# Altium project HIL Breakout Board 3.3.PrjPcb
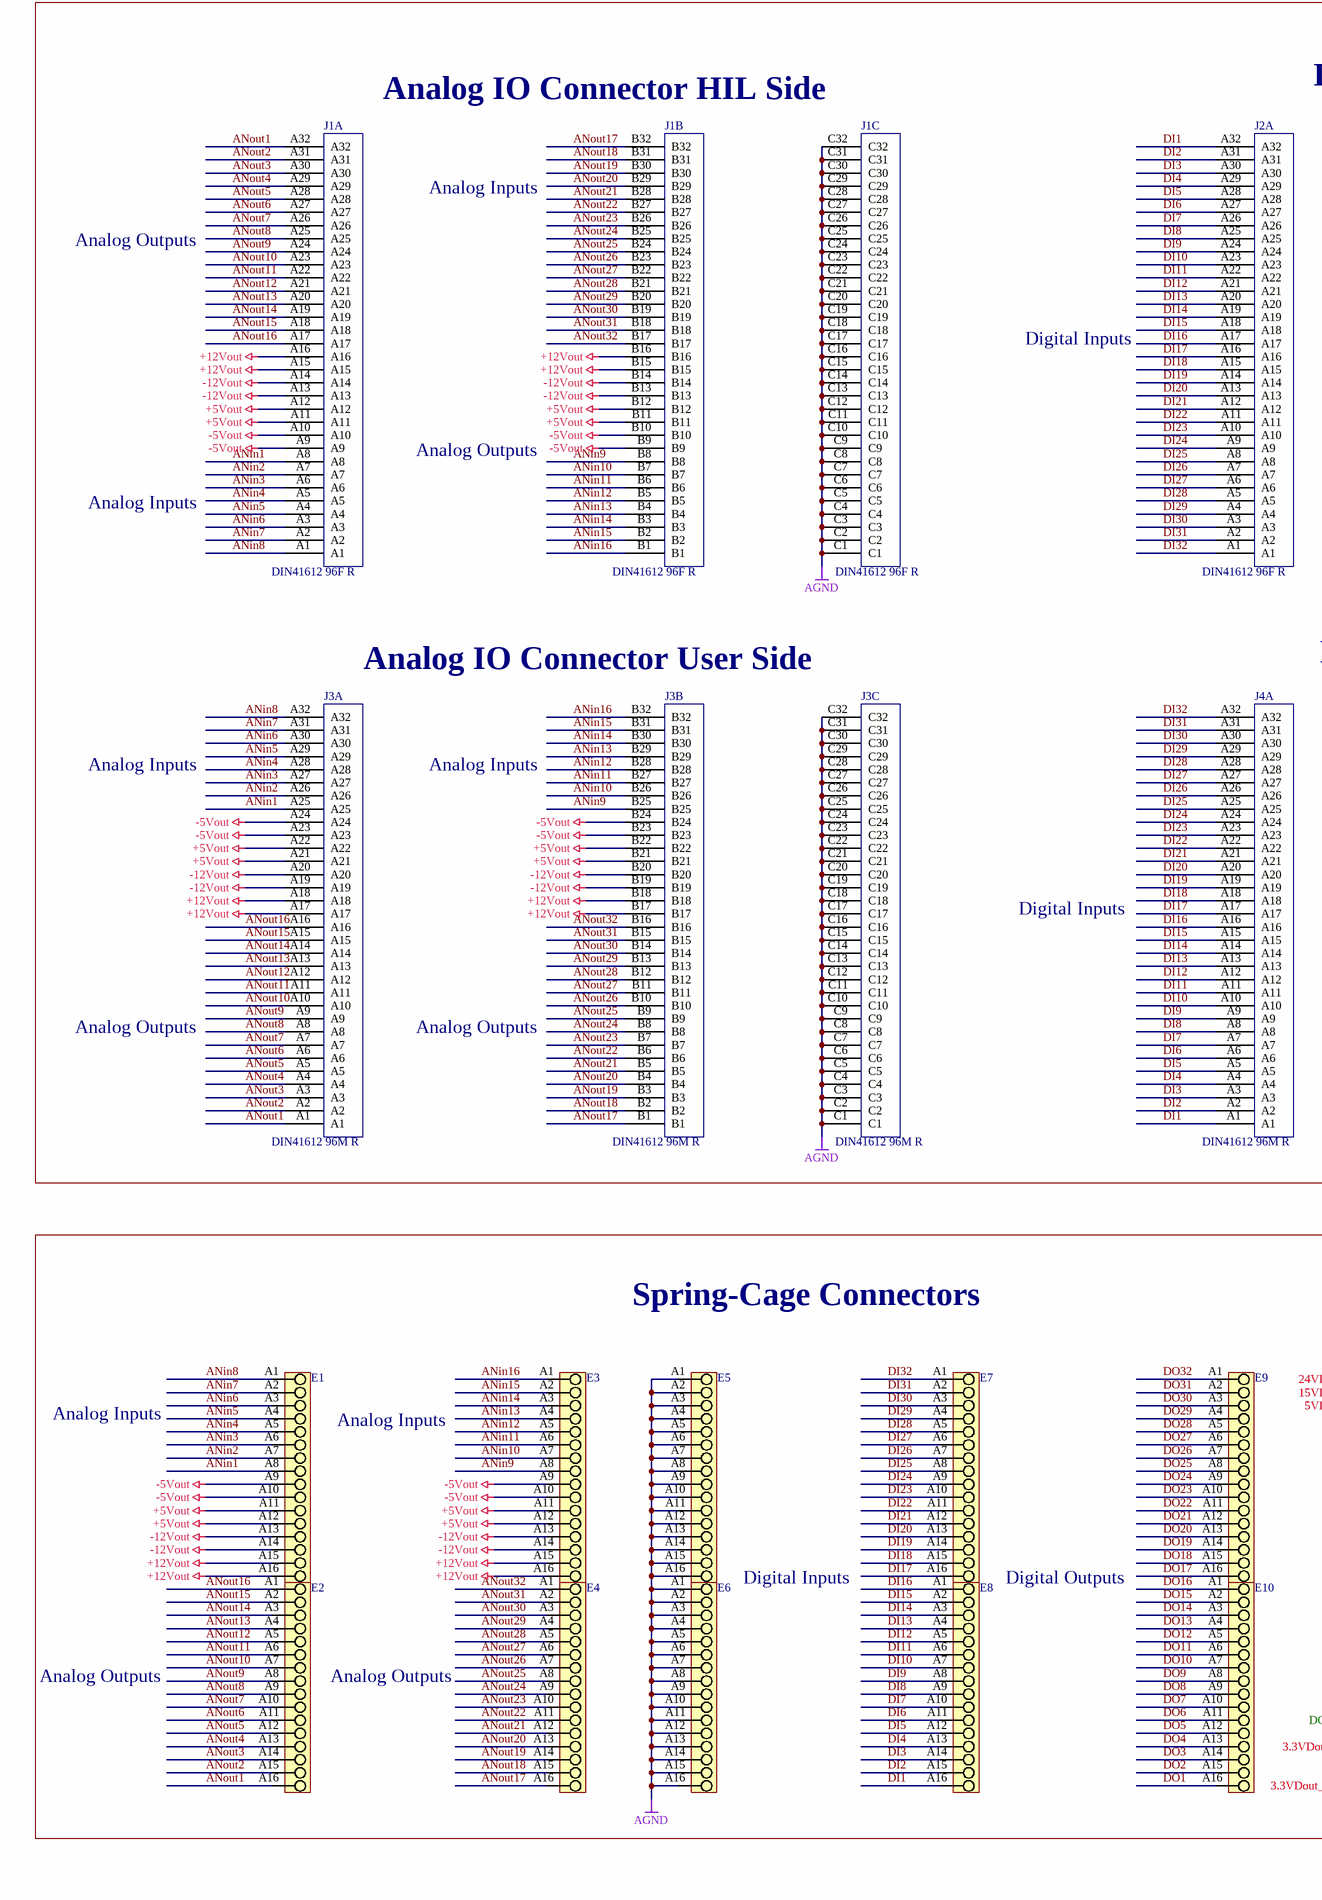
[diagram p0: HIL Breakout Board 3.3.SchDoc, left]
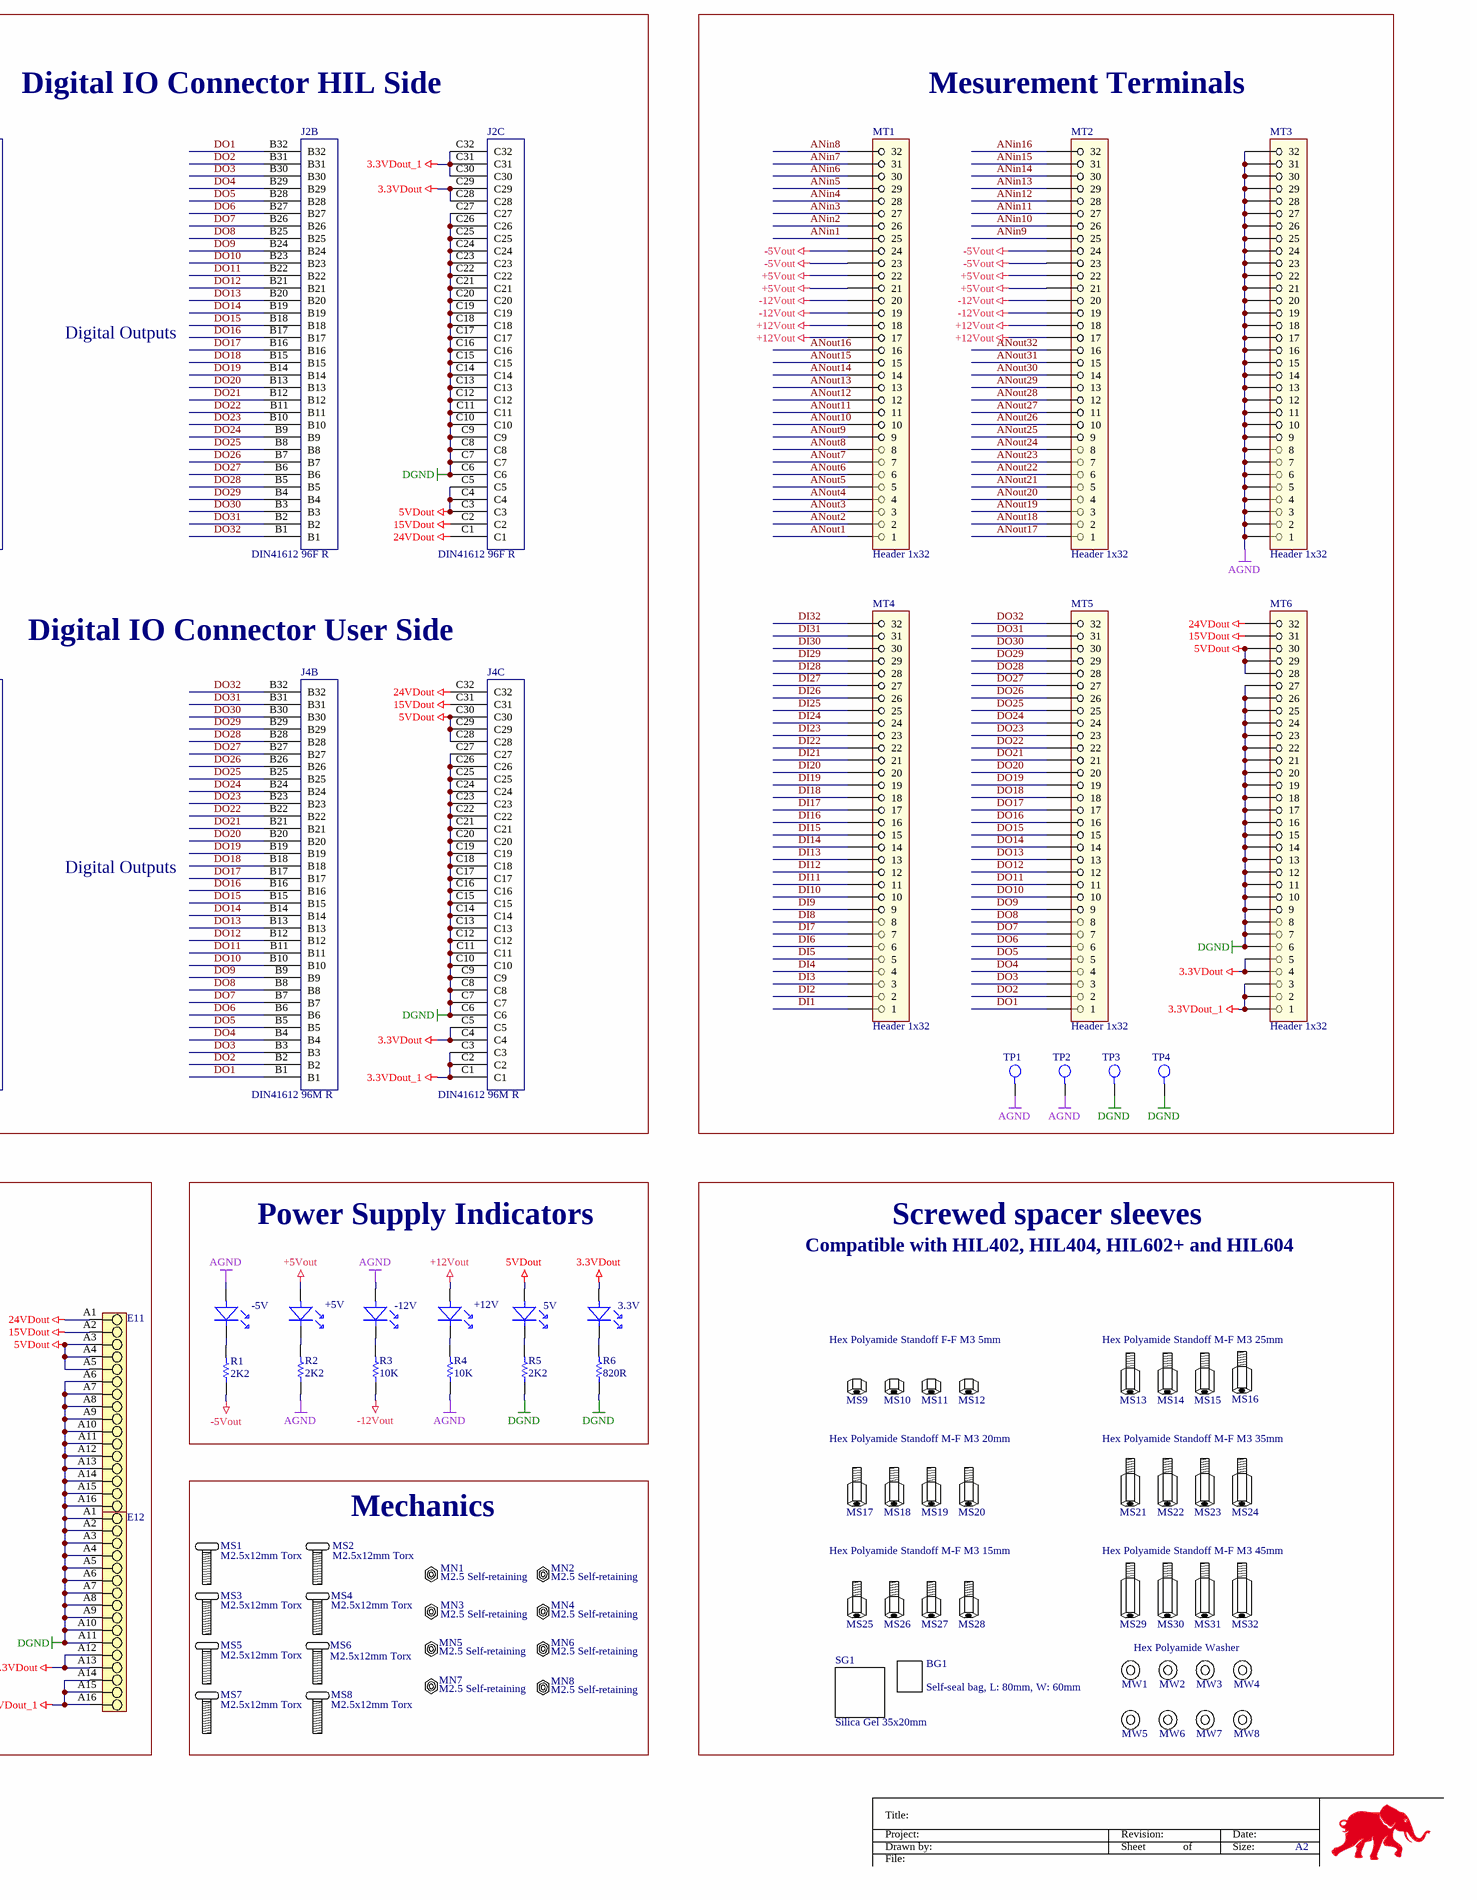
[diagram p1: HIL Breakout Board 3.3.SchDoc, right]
1 sheet, 88 parts. Net scope: global (net labels, ports and power ports of the same name join across sheets).
Board file: HIL Breakout Board 3.3.PcbDoc

## Sheet HIL Breakout Board 3.3.SchDoc: Snap-In Breakout Borad 3.3
size A2; Date: 02.06.2021.; DrawnBy: Ivan P. revised by Marko M.; Engineer: Default; Organization: Typhoon HIL; Revision: 3.3; SheetNumber: 1; SheetTotal: 1; PageSetup: Record=PageOptions¦CenterHorizontal=True¦CenterVertical=True¦PrintScale=0.97¦XCorrection=1.00¦YCorrection=1.00¦PrintKind=0¦BorderSize=5000000¦LeftOffset=0¦BottomOffset=0¦Orientation=2¦PaperLength=1000¦PaperWidth=1000¦Scale=100¦PaperSource=7¦PrintQuality=-4¦MediaType=1¦DitherType=10¦PaperKind=A4¦PrintScaleMode=1; Size: A2

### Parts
3.3V  LW Q38G-Q2OO-3K5L-1  [0603N]  (value not drawn)
5V  LW Q38G-Q2OO-3K5L-1  [0603N]  (value not drawn)
+5V  LW Q38G-Q2OO-3K5L-1  [0603N]  (value not drawn)
+12V  LW Q38G-Q2OO-3K5L-1  [0603N]  (value not drawn)
-5V  LW Q38G-Q2OO-3K5L-1  [0603N]  (value not drawn)
-12V  LW Q38G-Q2OO-3K5L-1  [0603N]  (value not drawn)
BG1  Self-seal bag, L: 80mm, W: 60mm  (mechanical)
E1  1885790000  [LSF_SMT_3_5_135_16]  (value not drawn)
E2  1885790000  [LSF_SMT_3_5_135_16]  (value not drawn)
E3  1885790000  [LSF_SMT_3_5_135_16]  (value not drawn)
E4  1885790000  [LSF_SMT_3_5_135_16]  (value not drawn)
E5  1885790000  [LSF_SMT_3_5_135_16]  (value not drawn)
E6  1885790000  [LSF_SMT_3_5_135_16]  (value not drawn)
E7  1885790000  [LSF_SMT_3_5_135_16]  (value not drawn)
E8  1885790000  [LSF_SMT_3_5_135_16]  (value not drawn)
E9  1885790000  [LSF_SMT_3_5_135_16]  (value not drawn)
E10  1885790000  [LSF_SMT_3_5_135_16]  (value not drawn)
E11  1885790000  [LSF_SMT_3_5_135_16]  (value not drawn)
E12  1885790000  [LSF_SMT_3_5_135_16]  (value not drawn)
J1  DIN41612 96F R  [HARTING DIN41612 96F R]  (parts A,B,C of 3)
J2  DIN41612 96F R  [HARTING DIN41612 96F R]  (parts A,B,C of 3)
J3  DIN41612 96M R  [HARTING DIN41612 96M R]  (parts A,B,C of 3)
J4  DIN41612 96M R  [HARTING DIN41612 96M R]  (parts A,B,C of 3)
MN1  M2.5 Self-retaining  (mechanical)
MN2  M2.5 Self-retaining  (mechanical)
MN3  M2.5 Self-retaining  (mechanical)
MN4  M2.5 Self-retaining  (mechanical)
MN5  M2.5 Self-retaining  (mechanical)
MN6  M2.5 Self-retaining  (mechanical)
MN7  M2.5 Self-retaining  (mechanical)
MN8  M2.5 Self-retaining  (mechanical)
MS1  M2.5x12mm Torx  (mechanical)
MS2  M2.5x12mm Torx  (mechanical)
MS3  M2.5x12mm Torx  (mechanical)
MS4  M2.5x12mm Torx  (mechanical)
MS5  M2.5x12mm Torx  (mechanical)
MS6  M2.5x12mm Torx  (mechanical)
MS7  M2.5x12mm Torx  (mechanical)
MS8  M2.5x12mm Torx  (mechanical)
MS9  Hex Polyamide Standoff F-F M3 5mm  (mechanical)
MS10  Hex Polyamide Standoff F-F M3 5mm  (value not drawn)  (mechanical)
MS11  Hex Polyamide Standoff F-F M3 5mm  (value not drawn)  (mechanical)
MS12  Hex Polyamide Standoff F-F M3 5mm  (value not drawn)  (mechanical)
MS13  Hex Polyamide Standoff M-F M3 25mm  (mechanical)
MS14  Hex Polyamide Standoff M-F M3 25mm  (value not drawn)  (mechanical)
MS15  Hex Polyamide Standoff M-F M3 25mm  (value not drawn)  (mechanical)
MS16  Hex Polyamide Standoff M-F M3 25mm  (value not drawn)  (mechanical)
MS17  Hex Polyamide Standoff M-F M3 20mm  (mechanical)
MS18  Hex Polyamide Standoff M-F M3 20mm  (value not drawn)  (mechanical)
MS19  Hex Polyamide Standoff M-F M3 20mm  (value not drawn)  (mechanical)
MS20  Hex Polyamide Standoff M-F M3 20mm  (value not drawn)  (mechanical)
MS21  Hex Polyamide Standoff M-F M3 35mm  (mechanical)
MS22  Hex Polyamide Standoff M-F M3 35mm  (value not drawn)  (mechanical)
MS23  Hex Polyamide Standoff M-F M3 35mm  (value not drawn)  (mechanical)
MS24  Hex Polyamide Standoff M-F M3 35mm  (value not drawn)  (mechanical)
MS25  Hex Polyamide Standoff M-F M3 15mm  (mechanical)
MS26  Hex Polyamide Standoff M-F M3 15mm  (value not drawn)  (mechanical)
MS27  Hex Polyamide Standoff M-F M3 15mm  (value not drawn)  (mechanical)
MS28  Hex Polyamide Standoff M-F M3 15mm  (value not drawn)  (mechanical)
MS29  Hex Polyamide Standoff M-F M3 45mm  (mechanical)
MS30  Hex Polyamide Standoff M-F M3 45mm  (value not drawn)  (mechanical)
MS31  Hex Polyamide Standoff M-F M3 45mm  (value not drawn)  (mechanical)
MS32  Hex Polyamide Standoff M-F M3 45mm  (value not drawn)  (mechanical)
MT1  Header 1x32  [HEADER1X32]
MT2  Header 1x32  [HEADER1X32]
MT3  Header 1x32  [HEADER1X32]
MT4  Header 1x32  [HEADER1X32]
MT5  Header 1x32  [HEADER1X32]
MT6  Header 1x32  [HEADER1X32]
MW1  Hex Polyamide Washer  (mechanical)
MW2  Hex Polyamide Washer  (value not drawn)  (mechanical)
MW3  Hex Polyamide Washer  (value not drawn)  (mechanical)
MW4  Hex Polyamide Washer  (value not drawn)  (mechanical)
MW5  Hex Polyamide Washer  (value not drawn)  (mechanical)
MW6  Hex Polyamide Washer  (value not drawn)  (mechanical)
MW7  Hex Polyamide Washer  (value not drawn)  (mechanical)
MW8  Hex Polyamide Washer  (value not drawn)  (mechanical)
R1  2K2  [RESC1608X06N]
R2  2K2  [RESC1608X06N]
R3  10K  [RESC1608X06N]
R4  10K  [RESC1608X06N]
R5  2K2  [RESC1608X06N]
R6  820R  [RESC1608X06N]
SG1  Silica Gel 35x20mm  (mechanical)
TP1  1.6mm hole, Qty.: 1PC, 2.4mm MAX PCB thickness  [TEST POINT 1.6mm HOLE]  (value not drawn)
TP2  1.6mm hole, Qty.: 1PC, 2.4mm MAX PCB thickness  [TEST POINT 1.6mm HOLE]  (value not drawn)
TP3  1.6mm hole, Qty.: 1PC, 2.4mm MAX PCB thickness  [TEST POINT 1.6mm HOLE]  (value not drawn)
TP4  1.6mm hole, Qty.: 1PC, 2.4mm MAX PCB thickness  [TEST POINT 1.6mm HOLE]  (value not drawn)

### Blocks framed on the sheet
Mesurement Terminals: MT1-MT6 TP1-TP4
Spring-Cage Connectors: E1-E12
Power Supply Indicators: 3.3V 5V +5V +12V -5V -12V R1-R6
Screwed spacer sleeves: BG1 MS9-MS32 MW1-MW8 SG1
Mechanics: MN1-MN8 MS1-MS8

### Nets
3.3VDout: 3.3V.2(A) E12.A12 E12.A13 J2.C28 J2.C29 J4.C4 J4.C5 MT6.4 MT6.5
3.3VDout_1: E12.A14 E12.A15 E12.A16 J2.C30 J2.C31 J2.C32 J4.C1 J4.C2 J4.C3 MT6.1 MT6.2 MT6.3
5VDout: 5V.2(A) E11.A3 E11.A4 E11.A5 J2.C3 J2.C4 J2.C5 J4.C28 J4.C29 J4.C30 MT6.28 MT6.29 MT6.30
15VDout: E11.A2 J2.C2 J4.C31 MT6.31
24VDout: E11.A1 J2.C1 J4.C32 MT6.32
+5Vout: +5V.2(A) E1.A11 E1.A12 E3.A11 E3.A12 J1.A11 J1.A12 J1.B11 J1.B12 J3.A21 J3.A22 J3.B21 J3.B22 MT1.21 MT1.22 MT2.21 MT2.22
+12Vout: +12V.2(A) E1.A15 E1.A16 E3.A15 E3.A16 J1.A15 J1.A16 J1.B15 J1.B16 J3.A17 J3.A18 J3.B17 J3.B18 MT1.17 MT1.18 MT2.17 MT2.18
-5Vout: E1.A9 E1.A10 E3.A9 E3.A10 J1.A9 J1.A10 J1.B9 J1.B10 J3.A23 J3.A24 J3.B23 J3.B24 MT1.23 MT1.24 MT2.23 MT2.24 R1.1
-12Vout: E1.A13 E1.A14 E3.A13 E3.A14 J1.A13 J1.A14 J1.B13 J1.B14 J3.A19 J3.A20 J3.B19 J3.B20 MT1.19 MT1.20 MT2.19 MT2.20 R3.1
AGND: -5V.2(A) -12V.2(A) E5.A1 E5.A2 E5.A3 E5.A4 E5.A5 E5.A6 E5.A7 E5.A8 E5.A9 E5.A10 E5.A11 E5.A12 E5.A13 E5.A14 E5.A15 E5.A16 E6.A1 E6.A2 E6.A3 E6.A4 E6.A5 E6.A6 E6.A7 E6.A8 E6.A9 E6.A10 E6.A11 E6.A12 E6.A13 E6.A14 E6.A15 E6.A16 J1.C1 J1.C2 J1.C3 J1.C4 J1.C5 J1.C6 J1.C7 J1.C8 J1.C9 J1.C10 J1.C11 J1.C12 J1.C13 J1.C14 J1.C15 J1.C16 J1.C17 J1.C18 J1.C19 J1.C20 J1.C21 J1.C22 J1.C23 J1.C24 J1.C25 J1.C26 J1.C27 J1.C28 J1.C29 J1.C30 J1.C31 J1.C32 J3.C1 J3.C2 J3.C3 J3.C4 J3.C5 J3.C6 J3.C7 J3.C8 J3.C9 J3.C10 J3.C11 J3.C12 J3.C13 J3.C14 J3.C15 J3.C16 J3.C17 J3.C18 J3.C19 J3.C20 J3.C21 J3.C22 J3.C23 J3.C24 J3.C25 J3.C26 J3.C27 J3.C28 J3.C29 J3.C30 J3.C31 J3.C32 MT3.1 MT3.2 MT3.3 MT3.4 MT3.5 MT3.6 MT3.7 MT3.8 MT3.9 MT3.10 MT3.11 MT3.12 MT3.13 MT3.14 MT3.15 MT3.16 MT3.17 MT3.18 MT3.19 MT3.20 MT3.21 MT3.22 MT3.23 MT3.24 MT3.25 MT3.26 MT3.27 MT3.28 MT3.29 MT3.30 MT3.31 MT3.32 R2.1 R4.1 TP1.1(TP) TP2.1(TP)
DGND: E11.A6 E11.A7 E11.A8 E11.A9 E11.A10 E11.A11 E11.A12 E11.A13 E11.A14 E11.A15 E11.A16 E12.A1 E12.A2 E12.A3 E12.A4 E12.A5 E12.A6 E12.A7 E12.A8 E12.A9 E12.A10 E12.A11 J2.C6 J2.C7 J2.C8 J2.C9 J2.C10 J2.C11 J2.C12 J2.C13 J2.C14 J2.C15 J2.C16 J2.C17 J2.C18 J2.C19 J2.C20 J2.C21 J2.C22 J2.C23 J2.C24 J2.C25 J2.C26 J2.C27 J4.C6 J4.C7 J4.C8 J4.C9 J4.C10 J4.C11 J4.C12 J4.C13 J4.C14 J4.C15 J4.C16 J4.C17 J4.C18 J4.C19 J4.C20 J4.C21 J4.C22 J4.C23 J4.C24 J4.C25 J4.C26 J4.C27 MT6.6 MT6.7 MT6.8 MT6.9 MT6.10 MT6.11 MT6.12 MT6.13 MT6.14 MT6.15 MT6.16 MT6.17 MT6.18 MT6.19 MT6.20 MT6.21 MT6.22 MT6.23 MT6.24 MT6.25 MT6.26 MT6.27 R5.1 R6.1 TP3.1(TP) TP4.1(TP)
ANin1: E1.A8 J1.A8 J3.A25 MT1.25
ANin2: E1.A7 J1.A7 J3.A26 MT1.26
ANin3: E1.A6 J1.A6 J3.A27 MT1.27
ANin4: E1.A5 J1.A5 J3.A28 MT1.28
ANin5: E1.A4 J1.A4 J3.A29 MT1.29
ANin6: E1.A3 J1.A3 J3.A30 MT1.30
ANin7: E1.A2 J1.A2 J3.A31 MT1.31
ANin8: E1.A1 J1.A1 J3.A32 MT1.32
ANin9: E3.A8 J1.B8 J3.B25 MT2.25
ANin10: E3.A7 J1.B7 J3.B26 MT2.26
ANin11: E3.A6 J1.B6 J3.B27 MT2.27
ANin12: E3.A5 J1.B5 J3.B28 MT2.28
ANin13: E3.A4 J1.B4 J3.B29 MT2.29
ANin14: E3.A3 J1.B3 J3.B30 MT2.30
ANin15: E3.A2 J1.B2 J3.B31 MT2.31
ANin16: E3.A1 J1.B1 J3.B32 MT2.32
ANout1: E2.A16 J1.A32 J3.A1 MT1.1
ANout2: E2.A15 J1.A31 J3.A2 MT1.2
ANout3: E2.A14 J1.A30 J3.A3 MT1.3
ANout4: E2.A13 J1.A29 J3.A4 MT1.4
ANout5: E2.A12 J1.A28 J3.A5 MT1.5
ANout6: E2.A11 J1.A27 J3.A6 MT1.6
ANout7: E2.A10 J1.A26 J3.A7 MT1.7
ANout8: E2.A9 J1.A25 J3.A8 MT1.8
ANout9: E2.A8 J1.A24 J3.A9 MT1.9
ANout10: E2.A7 J1.A23 J3.A10 MT1.10
ANout11: E2.A6 J1.A22 J3.A11 MT1.11
ANout12: E2.A5 J1.A21 J3.A12 MT1.12
ANout13: E2.A4 J1.A20 J3.A13 MT1.13
ANout14: E2.A3 J1.A19 J3.A14 MT1.14
ANout15: E2.A2 J1.A18 J3.A15 MT1.15
ANout16: E2.A1 J1.A17 J3.A16 MT1.16
ANout17: E4.A16 J1.B32 J3.B1 MT2.1
ANout18: E4.A15 J1.B31 J3.B2 MT2.2
ANout19: E4.A14 J1.B30 J3.B3 MT2.3
ANout20: E4.A13 J1.B29 J3.B4 MT2.4
ANout21: E4.A12 J1.B28 J3.B5 MT2.5
ANout22: E4.A11 J1.B27 J3.B6 MT2.6
ANout23: E4.A10 J1.B26 J3.B7 MT2.7
ANout24: E4.A9 J1.B25 J3.B8 MT2.8
ANout25: E4.A8 J1.B24 J3.B9 MT2.9
ANout26: E4.A7 J1.B23 J3.B10 MT2.10
ANout27: E4.A6 J1.B22 J3.B11 MT2.11
ANout28: E4.A5 J1.B21 J3.B12 MT2.12
ANout29: E4.A4 J1.B20 J3.B13 MT2.13
ANout30: E4.A3 J1.B19 J3.B14 MT2.14
ANout31: E4.A2 J1.B18 J3.B15 MT2.15
ANout32: E4.A1 J1.B17 J3.B16 MT2.16
DI1: E8.A16 J2.A32 J4.A1 MT4.1
DI2: E8.A15 J2.A31 J4.A2 MT4.2
DI3: E8.A14 J2.A30 J4.A3 MT4.3
DI4: E8.A13 J2.A29 J4.A4 MT4.4
DI5: E8.A12 J2.A28 J4.A5 MT4.5
DI6: E8.A11 J2.A27 J4.A6 MT4.6
DI7: E8.A10 J2.A26 J4.A7 MT4.7
DI8: E8.A9 J2.A25 J4.A8 MT4.8
DI9: E8.A8 J2.A24 J4.A9 MT4.9
DI10: E8.A7 J2.A23 J4.A10 MT4.10
DI11: E8.A6 J2.A22 J4.A11 MT4.11
DI12: E8.A5 J2.A21 J4.A12 MT4.12
DI13: E8.A4 J2.A20 J4.A13 MT4.13
DI14: E8.A3 J2.A19 J4.A14 MT4.14
DI15: E8.A2 J2.A18 J4.A15 MT4.15
DI16: E8.A1 J2.A17 J4.A16 MT4.16
DI17: E7.A16 J2.A16 J4.A17 MT4.17
DI18: E7.A15 J2.A15 J4.A18 MT4.18
DI19: E7.A14 J2.A14 J4.A19 MT4.19
DI20: E7.A13 J2.A13 J4.A20 MT4.20
DI21: E7.A12 J2.A12 J4.A21 MT4.21
DI22: E7.A11 J2.A11 J4.A22 MT4.22
DI23: E7.A10 J2.A10 J4.A23 MT4.23
DI24: E7.A9 J2.A9 J4.A24 MT4.24
DI25: E7.A8 J2.A8 J4.A25 MT4.25
DI26: E7.A7 J2.A7 J4.A26 MT4.26
DI27: E7.A6 J2.A6 J4.A27 MT4.27
DI28: E7.A5 J2.A5 J4.A28 MT4.28
DI29: E7.A4 J2.A4 J4.A29 MT4.29
DI30: E7.A3 J2.A3 J4.A30 MT4.30
DI31: E7.A2 J2.A2 J4.A31 MT4.31
DI32: E7.A1 J2.A1 J4.A32 MT4.32
DO1: E10.A16 J2.B32 J4.B1 MT5.1
DO2: E10.A15 J2.B31 J4.B2 MT5.2
DO3: E10.A14 J2.B30 J4.B3 MT5.3
DO4: E10.A13 J2.B29 J4.B4 MT5.4
DO5: E10.A12 J2.B28 J4.B5 MT5.5
DO6: E10.A11 J2.B27 J4.B6 MT5.6
DO7: E10.A10 J2.B26 J4.B7 MT5.7
DO8: E10.A9 J2.B25 J4.B8 MT5.8
DO9: E10.A8 J2.B24 J4.B9 MT5.9
DO10: E10.A7 J2.B23 J4.B10 MT5.10
DO11: E10.A6 J2.B22 J4.B11 MT5.11
DO12: E10.A5 J2.B21 J4.B12 MT5.12
DO13: E10.A4 J2.B20 J4.B13 MT5.13
DO14: E10.A3 J2.B19 J4.B14 MT5.14
DO15: E10.A2 J2.B18 J4.B15 MT5.15
DO16: E10.A1 J2.B17 J4.B16 MT5.16
DO17: E9.A16 J2.B16 J4.B17 MT5.17
DO18: E9.A15 J2.B15 J4.B18 MT5.18
DO19: E9.A14 J2.B14 J4.B19 MT5.19
DO20: E9.A13 J2.B13 J4.B20 MT5.20
DO21: E9.A12 J2.B12 J4.B21 MT5.21
DO22: E9.A11 J2.B11 J4.B22 MT5.22
DO23: E9.A10 J2.B10 J4.B23 MT5.23
DO24: E9.A9 J2.B9 J4.B24 MT5.24
DO25: E9.A8 J2.B8 J4.B25 MT5.25
DO26: E9.A7 J2.B7 J4.B26 MT5.26
DO27: E9.A6 J2.B6 J4.B27 MT5.27
DO28: E9.A5 J2.B5 J4.B28 MT5.28
DO29: E9.A4 J2.B4 J4.B29 MT5.29
DO30: E9.A3 J2.B3 J4.B30 MT5.30
DO31: E9.A2 J2.B2 J4.B31 MT5.31
DO32: E9.A1 J2.B1 J4.B32 MT5.32
Net3.3V_1: 3.3V.1(K) R6.2
Net5V_1: 5V.1(K) R5.2
Net+5V_1: +5V.1(K) R2.2
Net+12V_1: +12V.1(K) R4.2
Net-5V_1: -5V.1(K) R1.2
Net-12V_1: -12V.1(K) R3.2

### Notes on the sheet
- (near J1) Analog IO Connector HIL Side
- Digital IO Connector HIL Side
- Analog Outputs
- Analog Inputs
- Digital Inputs
- Digital Outputs
- (near J3) Analog IO Connector User Side
- (near J4) Digital IO Connector User Side
- Compatible with HIL402, HIL404, HIL602+ and HIL604
- (near E2) Analog Outputs
- Project:
- File:
- Drawn by:
- Title:
- Revision:
- Sheet
- of
- Size:
- Date:
- A2

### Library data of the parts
3.3V 5V +5V +12V -5V -12V = LW Q38G-Q2OO-3K5L-1: Standard LED - SMD White Diffused 8200K, If=15mA, Vf=2.85V, Case: 0603; Manufacturer: OSRAM Opto Semiconductors; Ordering Code: 720-LWQ38GQ2R23K5L1
BG1 = Self-seal bag L80 W60: Self-seal bag; L: 80mm; Width: 60mm; Thick: 45um; polyetylene; Ordering Code: PL.TOR60X80
E1-E12 = LSF_SMT_3_5_135_16__3_5_BK_TU: OMNIMATE Signal - series LSF; Manufacturer: Weidmüller; Side_termination_characteristic: closed side; Mounting_onto_the_PCB: Reflow solder connection; Pitch_mm: 3,5 mm; Pitch_inch: 0,138 inch; No_of_poles: 16; Contact_material: Cu-Leg; Contact_surface: tinned; Insulating_material: LCP GF; UL_94_flammability_rating: V-0; Rated_voltage_for_surge_voltage_class_pollution_degree_II_2: 320 V; Rated_current_min_no_of_poles_TU_20_deg_C: 17,5 A; Solid_min_H05_07_V_U: 0,2 mm²; Solid_max_H05_07_V_U: 1,5 mm²; Rated_voltage_use_group_B_UL_1059: 300 V; Rated_current_use_group_B_UL_1059: 12 A; Wire_cross_section_AWG_min_UL_1059: AWG 24; Wire_cross_section_AWG_max_UL_1059: AWG 16; Construction_type: PCB Terminal
J1 J2 = HARTING DIN41612 96F R: Connectors, Female connector, Wave soldering termination, Rated current: ‌2 A, Contacts: 96, Angled, Copper alloy, Noble metal, Mating side, Sn over Ni, Termination side, Performance level: 2, acc. to IEC 60603-2, Coding: Coding with loss of contacts, PCB fixing: With fixing flange, Thermoplastic resin, glass-fibre filled, RAL 7032 (pebble grey); Manufacturer Code: 09732966801; Ordering Code: 617-09-73-296-6801
J3 J4 = HARTING DIN41612 96M R: 96 pin ABC, RIGHT ANGLE, MALE; Manufacturer Code: 09031962921; Ordering Code: 617-09-03-196-2921
MN1-MN8 = Hex Nut M2.5 Self-retaining: Nut; hexagonal; M2.5; A2 stainless steel; Polyamide insert; 100PCS; Manufacturer: KRAFTBERG; Ordering Code: M2.5/D985-A2
MS1-MS8 = Screw M2.5 12mm Torx: Screw; M2,5x12 Head: cheese head; Torx TX08; A2 stainless steel; 100PCS; Manufacturer: BOSSARD; Manufacturer Code: 3108705; Ordering Code: B2.5X12/BN15857
MS9-MS12 = Hex Polyamide Standoff F-F M3 L5: Screwed spacer sleeve; hexagonal; polyamide; M3; L: 5mm; Manufacturer: DREMEC; Manufacturer Code: 185X05; Ordering Code: TFF-M3X5/DR185
MS13-MS16 = Hex Polyamide Standoff M-F M3 L25: Screwed spacer sleeve; hexagonal; polyamide; M3; L: 25mm; Manufacturer: DREMEC; Manufacturer Code: 285X25; Ordering Code: TFM-M3X25/DR285
MS17-MS20 = Hex Polyamide Standoff M-F M3 L20: Screwed spacer sleeve; hexagonal; polyamide; M3; L: 20mm; Manufacturer: DREMEC; Manufacturer Code: 285X20; Ordering Code: TFM-M3X20/DR285
MS21-MS24 = Hex Polyamide Standoff M-F M3 L35: Screwed spacer sleeve; hexagonal; polyamide; M3; L: 35mm; Manufacturer: DREMEC; Manufacturer Code: 285X35; Ordering Code: TFM-M3X35/DR285
MS25-MS28 = Hex Polyamide Standoff M-F M3 L15: Screwed spacer sleeve; hexagonal; polyamide; M3; L: 15mm; Manufacturer: DREMEC; Manufacturer Code: 285X15; Ordering Code: TFM-M3X15/DR285
MS29-MS32 = Hex Polyamide Standoff M-F M3 L45: Screwed spacer sleeve; hexagonal; polyamide; M3; L: 45mm; Manufacturer: DREMEC; Manufacturer Code: 285X45; Ordering Code: TFM-M3X45/DR285
MT1-MT6 = Header 1x32: BOARD-BOARD CONN, HEADER, 32WAY, 1ROW; Manufacturer: Harwin; Manufacturer Code: M20-9773246; Ordering Code: 855-M20-9773246
MW1-MW8 = Washer Flat M3 Polyamide: Manufacturer: Essentra; Ordering Code: 1340111
R1 R2 R5 = 2K2 1% 0.1W: 2K2 1% 0.1W RESC1608X06; Manufacturer: Panasonic; Manufacturer Code: ERJ-3EKF2201V; Ordering Code: 667-ERJ-3EKF2201V
R3 R4 = 10K 1% 0.1W: 10K 1% 0.1W RESC1608X06; Manufacturer: Panasonic; Manufacturer Code: ERJ-3EKF1002V; Ordering Code: 667-ERJ-3EKF1002V
R6 = 820R 1% 0.1W: 820R 1% 0.1W RESC1608X06; Manufacturer: Panasonic; Manufacturer Code: ERJ-3EKF8200V; Ordering Code: 667-ERJ-3EKF8200V
SG1 = Silica Gel 35x20mm: Moisture Absorbing Silica Gel; Size: 35 x 20 mm; Weight: 0.5g, Qty: 500 PCS.; Manufacturer: MULTICOMP PRO; Manufacturer Code: MP004367; Ordering Code: 3495105
TP1-TP4 = Test Point: MAX PCB thickness: 2.4mm; Mounting hole size: 1.6mm; Qty: 1PCS; Manufacturer: Keystone Electronics; Manufacturer Code: 5006; Ordering Code: 534-5006

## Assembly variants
Production: not fitted MT1 MT2 MT3 MT4 MT5 MT6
